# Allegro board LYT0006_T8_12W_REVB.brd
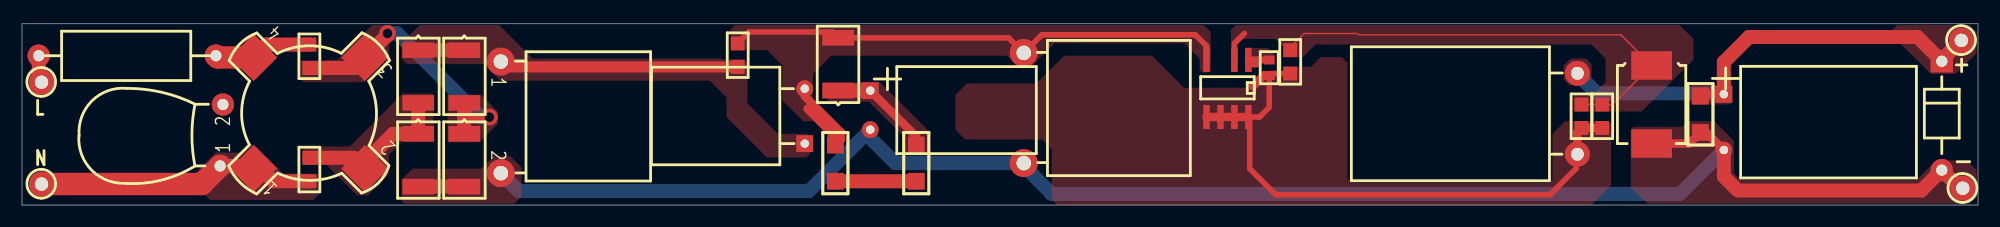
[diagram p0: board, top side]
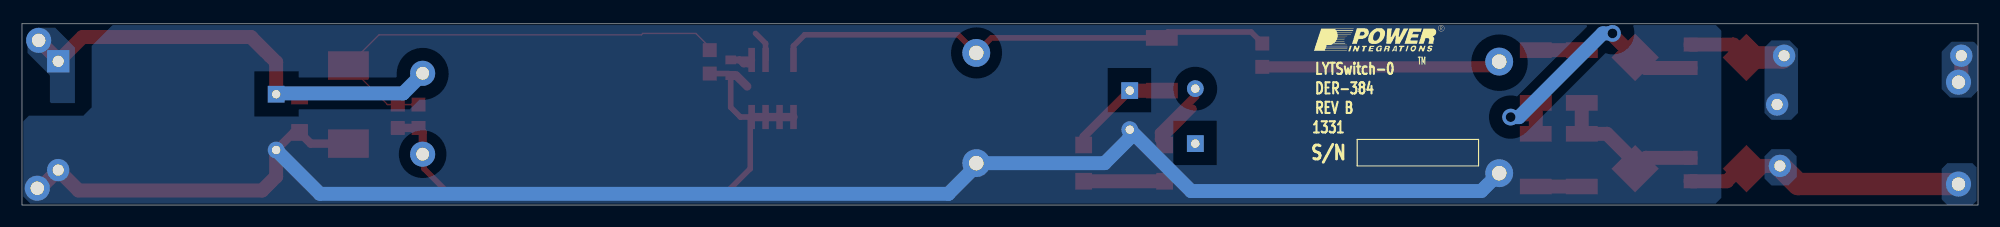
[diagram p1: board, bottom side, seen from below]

Outline 178.05 x 16.5 mm; copper layers: TOP, BOTTOM. Coordinates in mm from the lower left corner of the outline.
Outline path: 0,16.5 178.05,16.5 178.05,0 0,0 0,16.5

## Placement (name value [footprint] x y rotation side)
C1  100 nF  [PINPCAPRAD500X260400040H]  43.56 13.09 270 top
C2  330 nF  [PI_NP_CAPRAD512X299LS394D040_H]  91.19 13.85 270 top
C3  100 nF  [PISMC0603]  113.54 13.21 270 top
C4  22 uF  [PISMC0805]  115.44 14.1 270 top
C5  68 uF  [PIPOLCAPCLYD395X630LS200030H]  154.91 10.09 270 bottom
C6  1.0 uF  [PIPOLCAPCLYD320LS140030H]  77.22 8.64 270 top
D1  DL4007  [PISMDMLL4112]  36.07 14.1 270 top
D2  DL4007  [PISMDMLL4112]  40.26 14.1 270 top
D3  DL4007  [PISMDMLL4112]  36.07 6.48 270 top
D4  DL4007  [PISMDMLL4112]  40.26 6.48 270 top
D5  STTH2R06S  [PISMDO214AB12]  148.34 12.7 270 top
D6  DL4005-13-F  [PISMDMLL4112]  74.3 10.42 90 top
J1  PCB Terminal 22 AWG  [PI_HOLE_22AWG]  1.78 1.91 0 top
J2  PCB Terminal 22 AWG  [PI_HOLE_22AWG]  1.78 11.18 0 top
J3  PCB Terminal 22 AWG  [PI_HOLE_22AWG]  176.53 14.99 0 top
J4  PCB Terminal 22 AWG  [PI_HOLE_22AWG]  176.66 1.53 0 top
L1  10 mH  [PI_SM_IND_RENCO_RL9250]  21.08 3.31 135 top
L2  4.7 mH  [PI_CHOKE_450HX375LS197D030_H]  71.25 5.59 90 top
L3  3.9 mH  [PI_CHOKE_710HX450LS290D046_H]  141.58 4.63 90 top
NOREF  -  []  0 16.5 0 top
NOREF#2  -  []  0.64 0 90 top
NOREF#3  -  []  -228.6 -144.78 0 top
NOREF#4  -  []  -150.78 54.24 0 top
NOREF#5  -  []  60.45 13.97 180 bottom
R1  4.7 k  [PISMR0805]  65.15 12.58 90 top
R2  30.1  [PISMR0805]  141.96 7.01 90 top
R3  30.1  [PISMR0805]  143.84 7.01 90 top
R4  180 k  [PISMR1206]  74.04 5.47 270 top
R5  180 k  [PISMR1206]  81.41 2.16 90 top
R6  22 k  [PISMR0805]  26.16 2.16 90 top
R7  1 M  [PISMR1206]  152.78 9.91 270 top
R8  22 k  [PISMR0805]  26.16 14.61 270 top
RF1  10  [PI_2W_RESD145LS455D040]  18.54 13.59 180 top
RV1  275 Vac  [PI_DISC_354X220_LS220X10_040_H]  18.03 3.56 90 top
U1  LYT0006DN  [PIICSMDSO8]  111.63 13.21 180 top
VR1  1N4764A  [PIDV200X110X040DO41]  174.75 13.09 270 top

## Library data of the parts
C1 = CAP NP: alternate symbols: (pinpcaprad500x260400040h)
C2 = CAP NP: alternate symbols: (pi_np_caprad512x299ls394d040_h)
C3 C4 = CAP NP
C5 = CAP POL: alternate symbols: (pipolcapclyd395x630ls200030h)
C6 = CAP POL: alternate symbols: (pipolcapclyd320ls140030h)
D1-D6 = DIODE
J1-J4 = TERM_1PIN
L1 = INDUCTOR_4P_revD
L2 L3 = INDUCTOR
R1-R8 = R
RF1 = R: alternate symbols: (PI_2W_RES240LS500D040,pi_2w_resd145ls455d040)
RV1 = VARISTOR
U1 = LNK30X_SO8_DN
VR1 = DIODE_ZENER: alternate symbols: (pidax475x125040do41,pidv200x110x040do41wbead,pidax390x125040do41)

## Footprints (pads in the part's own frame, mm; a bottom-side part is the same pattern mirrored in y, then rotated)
PI_2W_RESD145LS455D040
  round 2.032 hole 1.016: 1(0.889,0) 2(17.018,0)
PI_CHOKE_450HX375LS197D030_H
  rect 1.524x1.524 hole 0.762: 1(0,0)
  round 1.524 hole 0.762: 2(5.004,0)
PI_CHOKE_710HX450LS290D046_H
  round 2.286 hole 1.168: 1(0,0) 2(7.366,0)
PI_DISC_354X220_LS220X10_040_H
  round 2.032 hole 1.016: 1(0,0) 2(5.588,-0.254)
PI_HOLE_22AWG
  round 2.286 hole 1.219: 1(0,0)
PI_NP_CAPRAD512X299LS394D040_H
  round 2.54 hole 1.321: 1(0,0) 2(10.033,0)
PI_SM_IND_RENCO_RL9250
  rect 3.048x3.048 smd: 1(0,0) 2(-7.163,-7.163) 3(0,-14.326) 4(7.163,-7.163)
PIDV200X110X040DO41
  rect 2.032x2.032 hole 1.016: 1(0,0)
  round 2.032 hole 1.016: 2(9.906,0)
PIICSMDSO8
  rect 0.599x2.2 smd: 1(0,0) 2(1.27,0) 4(3.81,0) 5(3.81,5.199) 6(2.54,5.199) 7(1.27,5.199) 8(0,5.199)
PINPCAPRAD500X260400040H
  round 2.54 hole 1.321: 1(0.025,0.025) 2(10.185,0.025)
PIPOLCAPCLYD320LS140030H
  rect 1.524x1.524 hole 0.762: 1(-1.778,0)
  round 1.524 hole 0.762: 2(1.778,0)
PIPOLCAPCLYD395X630LS200030H
  rect 1.524x1.524 hole 0.762: 1(0,0)
  round 1.524 hole 0.762: 2(5.08,0)
PISMC0603
  rect 0.813x0.965 smd: 1(0,0) 2(1.422,0)
PISMC0805
  rect 1.27x1.27 smd: 1(0,0) 2(2.134,0)
PISMDMLL4112
  rect 1.422x2.896 smd: 1(0,0) 2(4.801,0)
PISMDO214AB12
  rect 2.591x3.708 smd: 1(0,0) 2(7.112,0)
PISMR0805
  rect 1.27x1.27 smd: 1(0,0) 2(2.134,0)
PISMR1206
  rect 1.524x1.524 smd: 1(0,0) 2(3.302,0)

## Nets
SOURCE: C3.2 C4.2 L3.1 R2.1 R3.1 U1.5(S) U1.6 U1.7 U1.8
N40967: C1.1 D1.1 D2.1 L2.1 R1.1
N41017: C1.2 C2.2 C5.2 C6.2 D3.2 D4.2 D5.2 J4.1 R7.2 VR1.2
N41049: C4.1 D5.1 R2.2 R3.2 U1.2(FB)
N41137: C5.1 J3.1 L3.2 R7.1 VR1.1
N41161: J1.1 L1.1 R6.1 RV1.1
N41165: L1.4 R8.1 RF1.1 RV1.2
N41193: C2.1 D6.2 L2.2 R1.2 R4.1 U1.4(D)
N41233: C3.1 U1.1(BP)
N41297: J2.1 RF1.2
N42430: D2.2 D4.1 L1.3 R8.2
N42434: D1.2 D3.1 L1.2 R6.2
N45514: R4.2 R5.1
N45535: C6.1 D6.1 R5.2

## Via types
v1: diameter 1.524, hole 0.889, TOP to BOTTOM, 2 vias

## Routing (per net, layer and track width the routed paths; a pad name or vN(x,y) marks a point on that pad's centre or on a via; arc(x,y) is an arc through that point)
SOURCE: length 55.1
  TOP w0.508: C4.2 113.72,11.97 C3.2 113.54,8.89 112.65,8.01 112.64,8.01 U1.8 111.76,7.89 111.76,3.31 114.12,0.94 139.09,0.94 141.45,3.31 141.45,4.5 L3.1
  TOP w0.762: L3.1 141.58,6.63 R2.1 R3.1 ; U1.8 U1.7 U1.6 U1.5 ; 112.04,10.8 113.03,11.79 C3.2
N40967: length 26
  TOP w0.762: C1.1 44.07,12.58
  TOP w1.016: 44.07,12.58 R1.1
  TOP w1.27: D1.1 D2.1
N41017: length 157
  TOP w0.762: C5.2 153.31,6.61 R7.2 151.76,5.59 D5.2
  TOP w1.27: C5.2 154.91,2.6 156.18,1.33 172.9,1.33 174.75,3.18 176.4,1.53 J4.1 ; D3.2 D4.2
  BOTTOM w1.27: C1.2 45.21,1.27 71.63,1.27 C6.2 77.22,6.1 79.5,3.81 C2.2 91.19,3.56 93.73,1.02 150.93,1.02 C5.2
N41049: length 45.5
  TOP w0.127: C4.1 115.44,14.36 116.71,15.63 121.54,15.63 121.67,15.5 145.54,15.5 D5.1 144.78,9.15 R3.2 R2.2
  TOP w0.508: 111.28,15.63 110.36,14.71 U1.2
N41137: length 43.6
  TOP w0.762: R7.1 152.96,10.09 C5.1
  TOP w1.27: C5.1 154.91,13.01 157.2,15.3 172.54,15.3 VR1.1 174.75,13.21 J3.1
  BOTTOM w1.27: C5.1 154.84,10.16 143.36,10.16 141.58,11.94 L3.2
N41161: length 25.6
  TOP w1.27: R6.1 22.86,2.16 21.72,3.31 L1.1 20.83,3.56 RV1.1
  TOP w2.032: RV1.1 16.38,1.91 J1.1
N41165: length 9.1
  TOP w1.27: R8.1 22.26,14.61 L1.4
  TOP w2.032: L1.4 17.81,13.44 17.65,13.59
N41193: length 57.3
  TOP w0.508: U1.4 107.82,14.48 106.81,15.5 92.84,15.5 C2.1 89.81,15.22 D6.2 73.76,15.75 66.17,15.75 65.15,14.74 R1.2
  TOP w0.635: 71.25,9.91 L2.2
  TOP w0.762: 71.5,8.77 73.91,6.35 ; 74.04,6.35 R4.1 74.55,5.97 74.55,6.61 71.25,9.91
N41233: length 3.3
  TOP w0.635: 112.73,13.21 112.37,12.86 111.99,12.86 U1.1 112.73,13.21 ; 112.73,13.21 C3.1
N41297: length 2.5
  TOP w1.27: J2.1 1.52,11.43 1.52,13.59
N42430: length 26
  TOP w0.762: 40.26,8.01 v1(42.55,8.01)
  TOP w1.27: v1(33.27,15.63) 33.27,15.5 L1.3 30.25,12.48 R8.2 ; D2.2 D4.1
  BOTTOM w1.27: v1(33.27,15.63) 34.16,15.63 41.78,8.01 v1(42.55,8.01)
N42434: length 14.8
  TOP w1.27: D1.2 D3.1 33.78,6.48 31.21,3.91 L1.2 30.22,4.3 R6.2
N45514: length 7.4
  TOP w1.27: R4.2 R5.1
N45535: length 9.6
  TOP w0.762: C6.1 81.41,6.23 R5.2
  TOP w1.27: C6.1 D6.1

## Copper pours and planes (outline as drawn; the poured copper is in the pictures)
SOURCE on TOP: 144.4,7.62 140.46,7.62 139.32,6.48 139.32,2.29 139.06,2.04 121.03,2.04 120.65,2.42 120.65,12.96 120.14,13.47 118.24,13.47 117.35,12.58 114.81,12.58 114.55,12.32 113.03,12.32 111.38,10.67 105.79,10.67 102.87,13.59 94.87,13.59 92.33,11.05 85.98,11.05 84.96,10.04 84.96,6.86 85.85,5.97 92.84,5.97 93.73,5.08 93.73,0.51 94.23,0 142.88,0 144.65,1.78 144.65,7.37
N40967 on TOP: 35.05,12.83 34.54,13.34 34.54,14.74 36.2,16.39 43.43,16.39 46.48,13.34 65.66,13.34 66.04,12.96 66.04,9.28 68.83,6.48 71.5,6.48 71.75,6.23 71.75,4.7 71.37,4.32 67.82,4.32 64.14,8.01 64.14,9.78 62.61,11.31 43.56,11.31 42.04,12.83
N41017 on TOP: 34.54,0.39 34.54,2.29 35.56,3.31 41.78,3.31 42.93,4.45 44.45,4.45 45.47,3.43 45.47,0.77 44.83,0.13 34.8,0.13
N41017 on TOP: 146.43,1.66 146.43,6.86 146.69,7.12 151.13,7.12 151.64,7.62 154.05,7.62 155.83,5.85 155.83,2.93 156.46,2.29 172.47,2.29 174.24,4.07 177.04,4.07 177.93,3.18 177.93,0.77 177.29,0.13 147.96,0.13
N41017 on BOTTOM: 23.88,0.13 23.37,0.64 23.37,15.88 23.88,16.39 31.42,16.39 33.25,13.72 35.07,16.39 169.8,16.39 171.7,14.48 171.7,8.89 172.47,8.13 177.42,8.13 177.93,7.62 177.93,0.77 177.29,0.13 ; 9 cut-outs
N41049 on TOP: 110.06,12.12 110.06,15.96 110.49,16.39 150.88,16.39 152.15,15.12 152.15,13.21 147.45,8.51 141.35,8.51 141.22,8.64 141.22,9.91 141.48,10.16 143.13,10.16 144.15,11.18 144.15,13.34 142.88,14.61 117.73,14.61 116.59,13.47 114.81,13.47 114.81,14.41 114.1,15.12 111.12,15.12 110.62,14.61 110.62,12.12
N41137 on TOP: 152.02,9.15 155.45,9.15 155.7,9.4 155.7,10.8 155.57,10.93 152.02,10.93 151.89,10.8 151.89,9.28
N41137 on TOP: 170.31,16.01 170.69,16.39 177.29,16.39 177.93,15.75 177.93,13.85 176.02,11.94 173.74,11.94 170.31,15.37
N41137 on TOP: 142.37,13.34 140.97,13.34 140.34,12.7 140.34,11.43 140.84,10.93 142.24,10.93 142.88,11.56 142.88,12.83
N41137 on BOTTOM: 173.23,9.28 173.23,14.36 175.01,16.13 176.78,16.13 177.55,15.37 177.55,13.85 175.51,11.82 175.51,9.4 175.39,9.28
N41161 on TOP: 17.81,4.78 20.19,4.78 20.9,5.49 21.16,5.49 23.77,2.87 26.8,2.87 26.97,2.7 26.97,0.92 26.52,0.46 17.12,0.46 15.21,2.37 17.65,4.81 17.78,4.81
N41161 on BOTTOM: 2.79,3.81 0.51,3.81 0.13,3.43 0.13,0.39 0.51,0 2.79,0 3.3,0.51 3.3,3.31
N41161 on BOTTOM: 18.8,5.08 17.14,5.08 16.51,4.45 16.51,2.54 17.27,1.78 18.8,1.78 19.43,2.42 19.43,4.45
N41165 on BOTTOM: 16.38,8.39 16.38,14.23 17.14,14.99 18.8,14.99 19.43,14.36 19.43,8.39 18.8,7.75 17.02,7.75
N41193 on TOP: 74.8,4.7 74.8,6.48 72.01,9.28 72.01,11.94 73.66,13.59 89.66,13.59 90.68,12.58 91.82,12.58 93.98,14.74 105.79,14.74 107.19,13.34 107.19,12.32 107.44,12.07 108.08,12.07 108.2,12.2 108.2,15.75 107.57,16.39 64.9,16.39 64.52,16.01 64.52,14.1 67.82,14.1 69.22,12.7 69.22,9.53 71.12,7.62 72.14,7.62 73.15,6.61 73.28,6.35 73.28,4.83 73.41,4.7
N41233 on TOP: 111.33,12.65 111.33,14.25 111.38,14.3 113.41,14.3 114.05,13.67 114.05,12.83 114.02,12.81 112.06,12.81 111.84,12.58 111.4,12.58
N41297 on BOTTOM: 3.3,10.55 3.3,13.97 2.41,14.86 0.38,14.86 0,14.48 0,10.42 0.64,9.78 2.54,9.78
N42430 on TOP: 38.73,10.04 38.73,5.85 38.86,5.72 41.66,5.72 43.31,7.37 43.31,8.51 41.78,10.04
N42430 on TOP: 28.7,13.21 31.88,16.39 33.53,16.39 33.93,15.88 33.93,15.14 33.4,14.61 33.4,13.47 31.11,11.18 25.65,11.18 25.27,11.56 25.27,13.09 25.4,13.21
N42434 on TOP: 25.53,3.69 27.69,3.69 30.48,0.89 31.5,0.89 33.4,2.8 33.4,4.58 34.67,5.85 37.47,5.85 37.47,10.04 37.34,10.16 34.67,10.16 29.84,5.34 25.91,5.34 25.53,4.96
N45535 on TOP: 72.9,11.18 78.11,11.18 82.42,6.86 82.42,4.83 82.3,4.7 80.52,4.7 80.39,4.83 80.39,6.1 77.09,9.4 73.53,9.4 72.9,10.04

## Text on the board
Ref Des/Silkscreen Bottom: TM | LYTSwitch-0 | DER-384 | REV B | 1331 | S/N
Ref Des/Silkscreen Top: L | N
PEN17: 13   MATERIAL FR4 COPPER 2oz THICKNESS 0.031" DOUBLE SIDED.
User.5: FIGURE | SIZE | 30.0 | 35.0 | 40.0 | 46.0 | 48.0 | 52.0 | DRILL CHART: TOP to BOTTOM | ALL UNITS ARE IN MILS | PLATED | QTY | 13 | 2 | 6 | 4
User.7: SLOT
